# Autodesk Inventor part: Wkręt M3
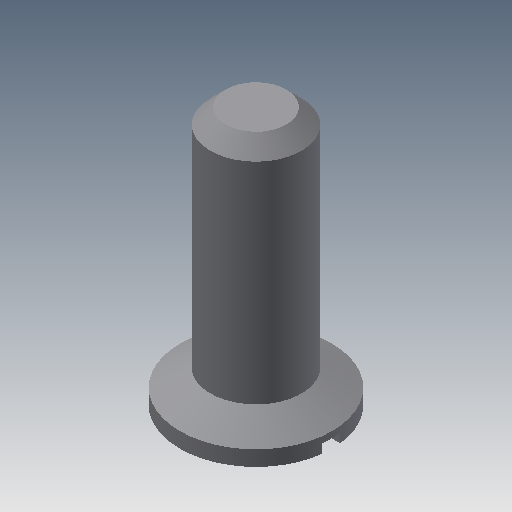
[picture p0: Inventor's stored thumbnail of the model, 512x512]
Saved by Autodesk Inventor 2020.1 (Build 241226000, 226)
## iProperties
Created: 2005-10
Part Number: Wkręt M3
Document SubType Name: Modeling
Designer: F.Stasiak
Density: 1 g/cm^3
Material: Ogólny
Appearance: Domyślna
Manager: www.cadconsulting.pl
Company: Fabian Stasiak CAD Consulting
Author: F.Stasiak
Subject: Zbiór ćwiczeń. Autodesk Inventor 2020. Kurs podstawowy
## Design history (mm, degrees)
sketch "Szkic1"
  geometry: L1 (0, 0)-(0, 8); L2 (0, 8)-(-1.5, 8); L3 (-1.5, 8)-(-1.5, 0.577); L4 (-1.5, 0.577)-(-2.5, 0); L5 (-2.5, 0)-(0, 0)
  constraints: 10 end point, 2 parallel, 1 perpendicular, 1 vertical
  dimensions: "d0" = 3 diameter of L3 L1; "d1" = 8 distance between parallel lines of L2 L5; "d2" = 5 diameter of L4.end L1; "d4" = 120 deg angle of L4 L3
revolve "Obrót1" sketch "Szkic1" stored, may be unused: angle "d5" = 90 deg
sketch "Szkic2"
  geometry: C1 r 2.5 at (0, 0) reference
extrude "Wyciągnięcie proste1" join sketch "Szkic2" distance "d6" = 0.5; taper "d7" = 0 deg
chamfer "Faza1" distance "d8" = 0.5; stored, may be unused: second distance "d9" = 2, angle "d10" = 45 deg
sketch "Szkic3"
  geometry: L1 (-0.5, -2.5)-(-0.5, 2.5) reference; L2 (-0.5, 0.307)-(-0.2, 0.307); L3 (-0.2, 0.307)-(-0.2, -0.293); L4 (-0.2, -0.293)-(-0.5, -0.293); L5 (-0.5, -0.293)-(-0.5, 0.307); 1 further point
  constraints: 8 end point, 2 parallel, 1 horizontal, 1 midpoint, 1 perpendicular, 1 point on line
  dimensions: "d11" = 0.6 distance of L4.end L2.start; "d12" = 0.3 distance of L3.end L4.end
extrude "Wyciągnięcie proste2" cut sketch "Szkic3" extent not by distance; stored distance "d13" = 0.5; taper "d14" = 0 deg
node "Bryła1"
node "Korpusy bryłowe"
node "Korpusy powierzchniowe"
node "Pętla rzutowana1"
